// Mitsubishi GX Works2 project: Elevator   PLC: Q00J
// エレベータ制御

PROGRAM MAIN
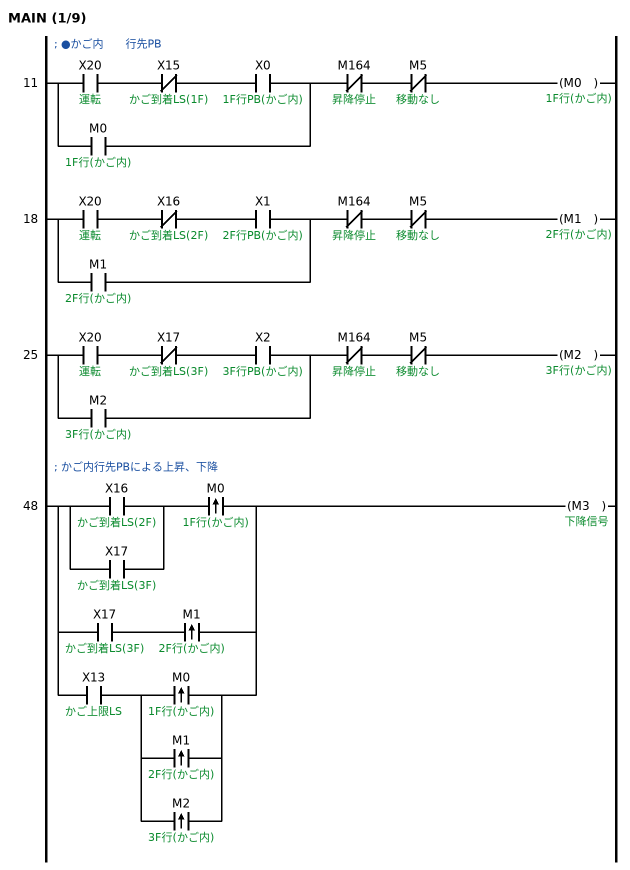
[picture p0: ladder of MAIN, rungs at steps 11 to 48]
; ●かご内　　行先PB
11    LD      X20  ; 運転
      ANI     X15  ; かご到着LS(1F)
      AND     X0  ; 1F行PB(かご内)
      OR      M0  ; 1F行(かご内)
      ANI     M164  ; 昇降停止
      ANI     M5  ; 移動なし
      OUT     M0  ; 1F行(かご内)
18    LD      X20  ; 運転
      ANI     X16  ; かご到着LS(2F)
      AND     X1  ; 2F行PB(かご内)
      OR      M1  ; 2F行(かご内)
      ANI     M164  ; 昇降停止
      ANI     M5  ; 移動なし
      OUT     M1  ; 2F行(かご内)
25    LD      X20  ; 運転
      ANI     X17  ; かご到着LS(3F)
      AND     X2  ; 3F行PB(かご内)
      OR      M2  ; 3F行(かご内)
      ANI     M164  ; 昇降停止
      ANI     M5  ; 移動なし
      OUT     M2  ; 3F行(かご内)
; かご内行先PBによる上昇、下降
48    LD      X16  ; かご到着LS(2F)
      OR      X17  ; かご到着LS(3F)
      ANDP    M0  ; 1F行(かご内)
      LD      X17  ; かご到着LS(3F)
      ANDP    M1  ; 2F行(かご内)
      ORB
      LD      X13  ; かご上限LS
      LDP     M0  ; 1F行(かご内)
      ORP     M1  ; 2F行(かご内)
      ORP     M2  ; 3F行(かご内)
      ANB
      ORB
      OUT     M3  ; 下降信号
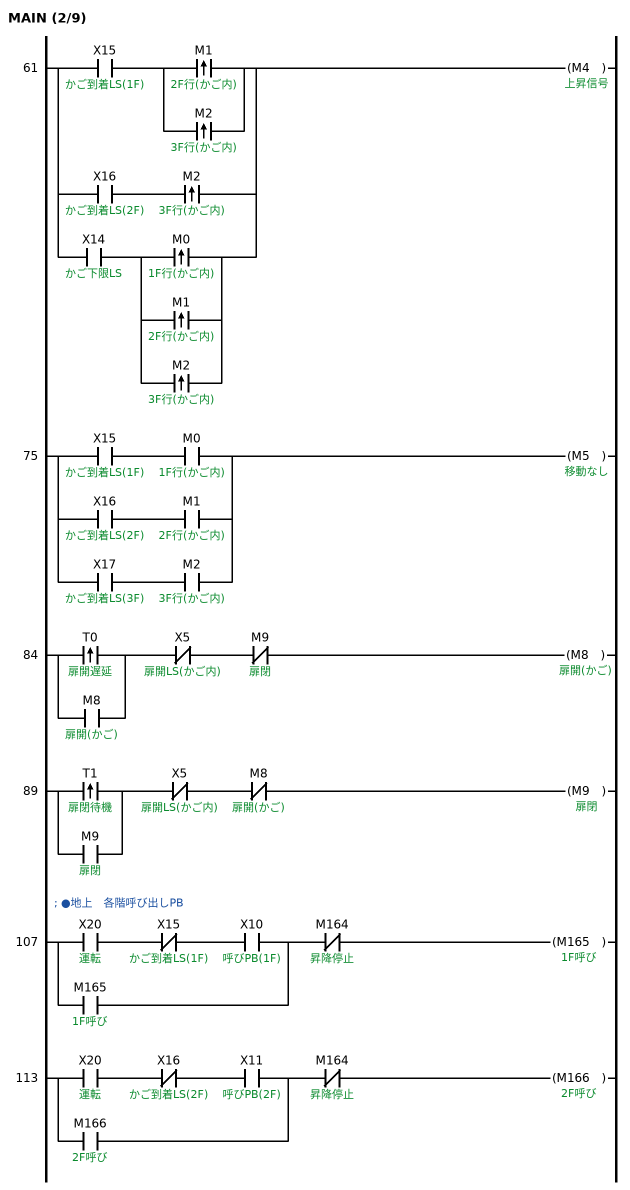
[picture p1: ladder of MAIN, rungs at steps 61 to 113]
61    LD      X15  ; かご到着LS(1F)
      LDP     M1  ; 2F行(かご内)
      ORP     M2  ; 3F行(かご内)
      ANB
      LD      X16  ; かご到着LS(2F)
      ANDP    M2  ; 3F行(かご内)
      ORB
      LD      X14  ; かご下限LS
      LDP     M0  ; 1F行(かご内)
      ORP     M1  ; 2F行(かご内)
      ORP     M2  ; 3F行(かご内)
      ANB
      ORB
      OUT     M4  ; 上昇信号
75    LD      X15  ; かご到着LS(1F)
      AND     M0  ; 1F行(かご内)
      LD      X16  ; かご到着LS(2F)
      AND     M1  ; 2F行(かご内)
      ORB
      LD      X17  ; かご到着LS(3F)
      AND     M2  ; 3F行(かご内)
      ORB
      OUT     M5  ; 移動なし
84    LDP     T0  ; 扉開遅延
      OR      M8  ; 扉開(かご)
      ANI     X5  ; 扉開LS(かご内)
      ANI     M9  ; 扉閉
      OUT     M8  ; 扉開(かご)
89    LDP     T1  ; 扉閉待機
      OR      M9  ; 扉閉
      ANI     X5  ; 扉開LS(かご内)
      ANI     M8  ; 扉開(かご)
      OUT     M9  ; 扉閉
; ●地上　各階呼び出しPB
107   LD      X20  ; 運転
      ANI     X15  ; かご到着LS(1F)
      AND     X10  ; 呼びPB(1F)
      OR      M165  ; 1F呼び
      ANI     M164  ; 昇降停止
      OUT     M165  ; 1F呼び
113   LD      X20  ; 運転
      ANI     X16  ; かご到着LS(2F)
      AND     X11  ; 呼びPB(2F)
      OR      M166  ; 2F呼び
      ANI     M164  ; 昇降停止
      OUT     M166  ; 2F呼び
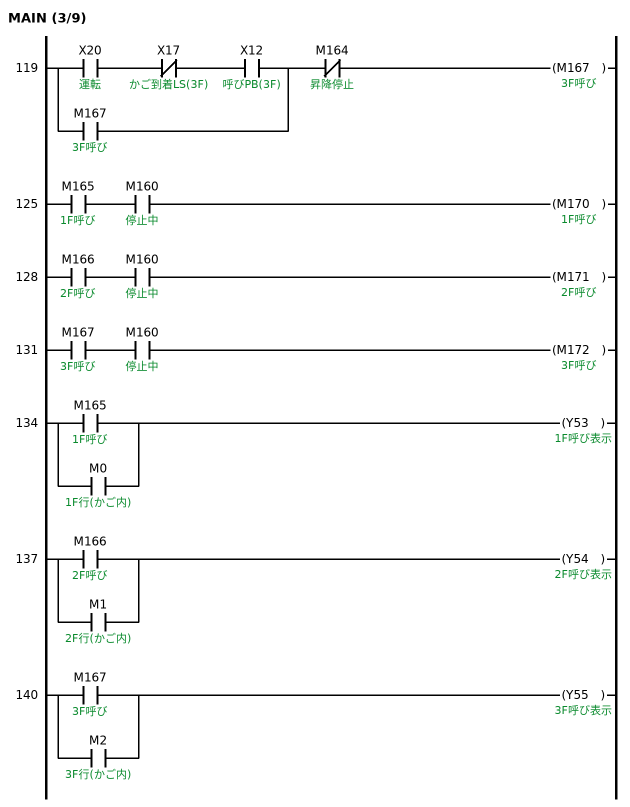
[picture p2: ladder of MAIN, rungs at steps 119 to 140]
119   LD      X20  ; 運転
      ANI     X17  ; かご到着LS(3F)
      AND     X12  ; 呼びPB(3F)
      OR      M167  ; 3F呼び
      ANI     M164  ; 昇降停止
      OUT     M167  ; 3F呼び
125   LD      M165  ; 1F呼び
      AND     M160  ; 停止中
      OUT     M170  ; 1F呼び
128   LD      M166  ; 2F呼び
      AND     M160  ; 停止中
      OUT     M171  ; 2F呼び
131   LD      M167  ; 3F呼び
      AND     M160  ; 停止中
      OUT     M172  ; 3F呼び
134   LD      M165  ; 1F呼び
      OR      M0  ; 1F行(かご内)
      OUT     Y53  ; 1F呼び表示
137   LD      M166  ; 2F呼び
      OR      M1  ; 2F行(かご内)
      OUT     Y54  ; 2F呼び表示
140   LD      M167  ; 3F呼び
      OR      M2  ; 3F行(かご内)
      OUT     Y55  ; 3F呼び表示
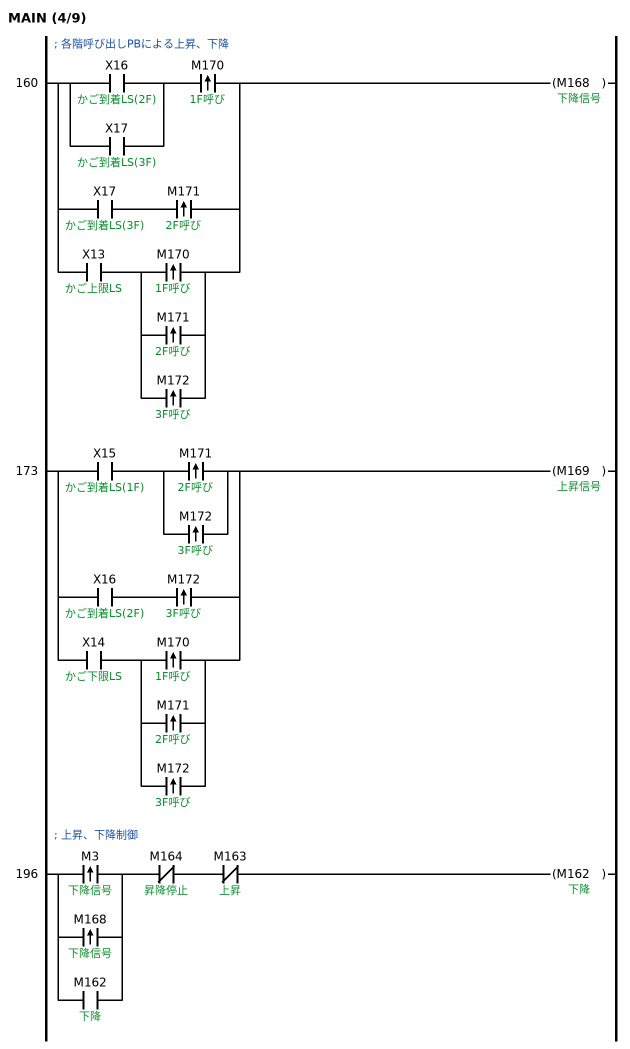
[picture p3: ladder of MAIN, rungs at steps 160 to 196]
; 各階呼び出しPBによる上昇、下降
160   LD      X16  ; かご到着LS(2F)
      OR      X17  ; かご到着LS(3F)
      ANDP    M170  ; 1F呼び
      LD      X17  ; かご到着LS(3F)
      ANDP    M171  ; 2F呼び
      ORB
      LD      X13  ; かご上限LS
      LDP     M170  ; 1F呼び
      ORP     M171  ; 2F呼び
      ORP     M172  ; 3F呼び
      ANB
      ORB
      OUT     M168  ; 下降信号
173   LD      X15  ; かご到着LS(1F)
      LDP     M171  ; 2F呼び
      ORP     M172  ; 3F呼び
      ANB
      LD      X16  ; かご到着LS(2F)
      ANDP    M172  ; 3F呼び
      ORB
      LD      X14  ; かご下限LS
      LDP     M170  ; 1F呼び
      ORP     M171  ; 2F呼び
      ORP     M172  ; 3F呼び
      ANB
      ORB
      OUT     M169  ; 上昇信号
; 上昇、下降制御
196   LDP     M3  ; 下降信号
      ORP     M168  ; 下降信号
      OR      M162  ; 下降
      ANI     M164  ; 昇降停止
      ANI     M163  ; 上昇
      OUT     M162  ; 下降
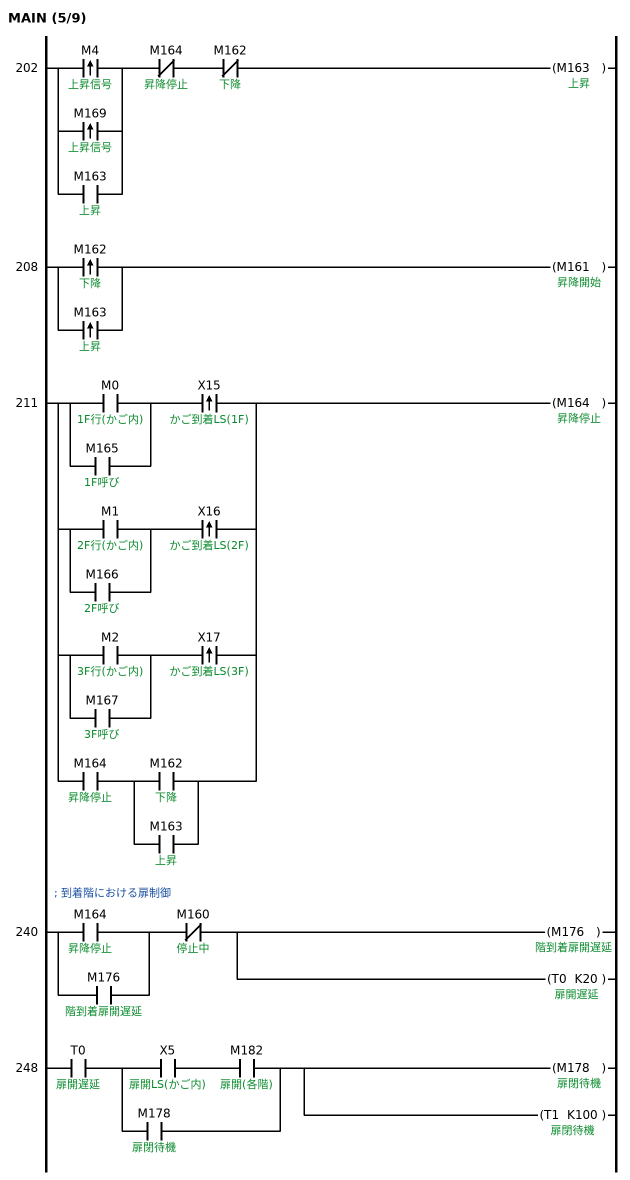
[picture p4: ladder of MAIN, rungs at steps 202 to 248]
202   LDP     M4  ; 上昇信号
      ORP     M169  ; 上昇信号
      OR      M163  ; 上昇
      ANI     M164  ; 昇降停止
      ANI     M162  ; 下降
      OUT     M163  ; 上昇
208   LDP     M162  ; 下降
      ORP     M163  ; 上昇
      OUT     M161  ; 昇降開始
211   LD      M0  ; 1F行(かご内)
      OR      M165  ; 1F呼び
      ANDP    X15  ; かご到着LS(1F)
      LD      M1  ; 2F行(かご内)
      OR      M166  ; 2F呼び
      ANDP    X16  ; かご到着LS(2F)
      ORB
      LD      M2  ; 3F行(かご内)
      OR      M167  ; 3F呼び
      ANDP    X17  ; かご到着LS(3F)
      ORB
      LD      M164  ; 昇降停止
      LD      M162  ; 下降
      OR      M163  ; 上昇
      ANB
      ORB
      OUT     M164  ; 昇降停止
; 到着階における扉制御
240   LD      M164  ; 昇降停止
      OR      M176  ; 階到着扉開遅延
      ANI     M160  ; 停止中
      OUT     M176  ; 階到着扉開遅延
      OUT     T0 K20  ; 扉開遅延
248   LD      T0  ; 扉開遅延
      LD      X5  ; 扉開LS(かご内)
      AND     M182  ; 扉開(各階)
      OR      M178  ; 扉閉待機
      ANB
      OUT     M178  ; 扉閉待機
      OUT     T1 K100  ; 扉閉待機
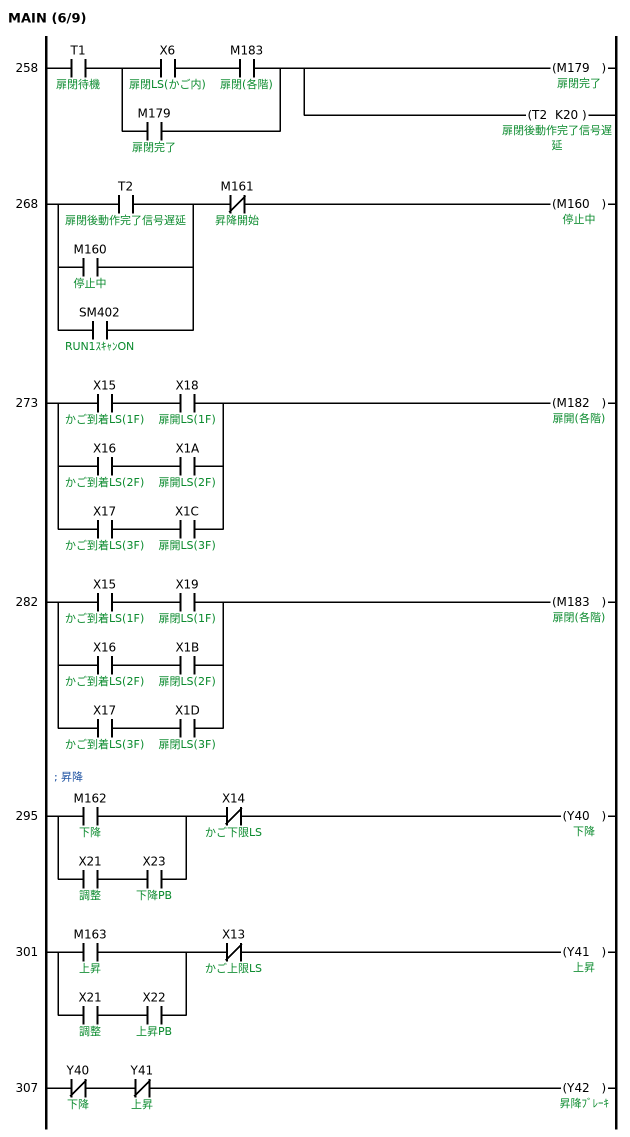
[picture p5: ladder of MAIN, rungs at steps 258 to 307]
258   LD      T1  ; 扉閉待機
      LD      X6  ; 扉閉LS(かご内)
      AND     M183  ; 扉閉(各階)
      OR      M179  ; 扉閉完了
      ANB
      OUT     M179  ; 扉閉完了
      OUT     T2 K20  ; 扉閉後動作完了信号遅延
268   LD      T2  ; 扉閉後動作完了信号遅延
      OR      M160  ; 停止中
      OR      SM402  ; RUN1ｽｷｬﾝON
      ANI     M161  ; 昇降開始
      OUT     M160  ; 停止中
273   LD      X15  ; かご到着LS(1F)
      AND     X18  ; 扉開LS(1F)
      LD      X16  ; かご到着LS(2F)
      AND     X1A  ; 扉開LS(2F)
      ORB
      LD      X17  ; かご到着LS(3F)
      AND     X1C  ; 扉開LS(3F)
      ORB
      OUT     M182  ; 扉開(各階)
282   LD      X15  ; かご到着LS(1F)
      AND     X19  ; 扉閉LS(1F)
      LD      X16  ; かご到着LS(2F)
      AND     X1B  ; 扉閉LS(2F)
      ORB
      LD      X17  ; かご到着LS(3F)
      AND     X1D  ; 扉閉LS(3F)
      ORB
      OUT     M183  ; 扉閉(各階)
; 昇降
295   LD      M162  ; 下降
      LD      X21  ; 調整
      AND     X23  ; 下降PB
      ORB
      ANI     X14  ; かご下限LS
      OUT     Y40  ; 下降
301   LD      M163  ; 上昇
      LD      X21  ; 調整
      AND     X22  ; 上昇PB
      ORB
      ANI     X13  ; かご上限LS
      OUT     Y41  ; 上昇
307   LDI     Y40  ; 下降
      ANI     Y41  ; 上昇
      OUT     Y42  ; 昇降ﾌﾞﾚｰｷ
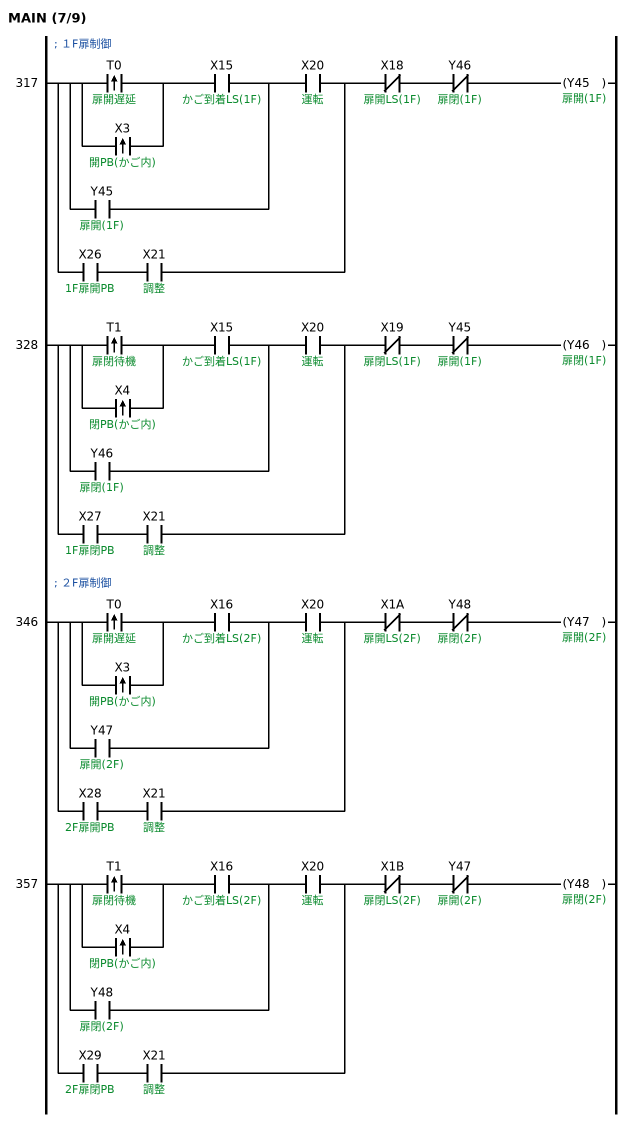
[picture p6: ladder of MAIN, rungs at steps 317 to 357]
; １F扉制御
317   LDP     T0  ; 扉開遅延
      ORP     X3  ; 開PB(かご内)
      AND     X15  ; かご到着LS(1F)
      OR      Y45  ; 扉開(1F)
      AND     X20  ; 運転
      LD      X26  ; 1F扉開PB
      AND     X21  ; 調整
      ORB
      ANI     X18  ; 扉開LS(1F)
      ANI     Y46  ; 扉閉(1F)
      OUT     Y45  ; 扉開(1F)
328   LDP     T1  ; 扉閉待機
      ORP     X4  ; 閉PB(かご内)
      AND     X15  ; かご到着LS(1F)
      OR      Y46  ; 扉閉(1F)
      AND     X20  ; 運転
      LD      X27  ; 1F扉閉PB
      AND     X21  ; 調整
      ORB
      ANI     X19  ; 扉閉LS(1F)
      ANI     Y45  ; 扉開(1F)
      OUT     Y46  ; 扉閉(1F)
; ２F扉制御
346   LDP     T0  ; 扉開遅延
      ORP     X3  ; 開PB(かご内)
      AND     X16  ; かご到着LS(2F)
      OR      Y47  ; 扉開(2F)
      AND     X20  ; 運転
      LD      X28  ; 2F扉開PB
      AND     X21  ; 調整
      ORB
      ANI     X1A  ; 扉開LS(2F)
      ANI     Y48  ; 扉閉(2F)
      OUT     Y47  ; 扉開(2F)
357   LDP     T1  ; 扉閉待機
      ORP     X4  ; 閉PB(かご内)
      AND     X16  ; かご到着LS(2F)
      OR      Y48  ; 扉閉(2F)
      AND     X20  ; 運転
      LD      X29  ; 2F扉閉PB
      AND     X21  ; 調整
      ORB
      ANI     X1B  ; 扉閉LS(2F)
      ANI     Y47  ; 扉開(2F)
      OUT     Y48  ; 扉閉(2F)
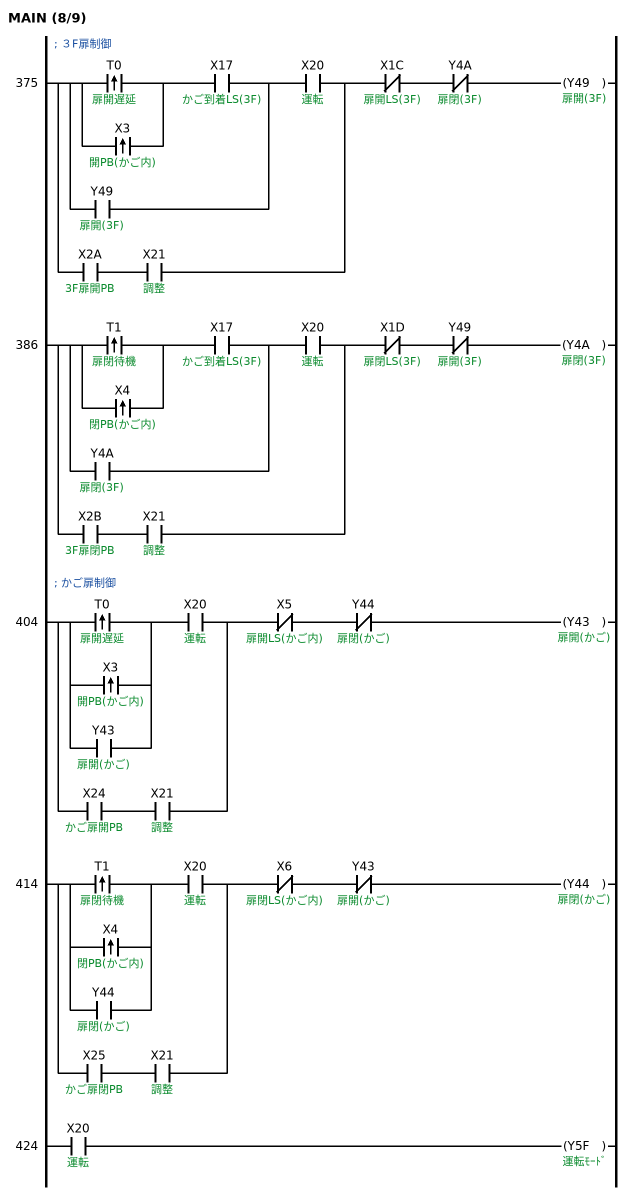
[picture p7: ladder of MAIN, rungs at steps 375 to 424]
; ３F扉制御
375   LDP     T0  ; 扉開遅延
      ORP     X3  ; 開PB(かご内)
      AND     X17  ; かご到着LS(3F)
      OR      Y49  ; 扉開(3F)
      AND     X20  ; 運転
      LD      X2A  ; 3F扉開PB
      AND     X21  ; 調整
      ORB
      ANI     X1C  ; 扉開LS(3F)
      ANI     Y4A  ; 扉閉(3F)
      OUT     Y49  ; 扉開(3F)
386   LDP     T1  ; 扉閉待機
      ORP     X4  ; 閉PB(かご内)
      AND     X17  ; かご到着LS(3F)
      OR      Y4A  ; 扉閉(3F)
      AND     X20  ; 運転
      LD      X2B  ; 3F扉閉PB
      AND     X21  ; 調整
      ORB
      ANI     X1D  ; 扉閉LS(3F)
      ANI     Y49  ; 扉開(3F)
      OUT     Y4A  ; 扉閉(3F)
; かご扉制御
404   LDP     T0  ; 扉開遅延
      ORP     X3  ; 開PB(かご内)
      OR      Y43  ; 扉開(かご)
      AND     X20  ; 運転
      LD      X24  ; かご扉開PB
      AND     X21  ; 調整
      ORB
      ANI     X5  ; 扉開LS(かご内)
      ANI     Y44  ; 扉閉(かご)
      OUT     Y43  ; 扉開(かご)
414   LDP     T1  ; 扉閉待機
      ORP     X4  ; 閉PB(かご内)
      OR      Y44  ; 扉閉(かご)
      AND     X20  ; 運転
      LD      X25  ; かご扉閉PB
      AND     X21  ; 調整
      ORB
      ANI     X6  ; 扉閉LS(かご内)
      ANI     Y43  ; 扉開(かご)
      OUT     Y44  ; 扉閉(かご)
424   LD      X20  ; 運転
      OUT     Y5F  ; 運転ﾓｰﾄﾞ
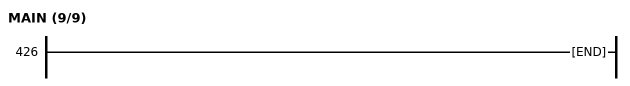
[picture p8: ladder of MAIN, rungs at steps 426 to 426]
426   END
END_PROGRAM
